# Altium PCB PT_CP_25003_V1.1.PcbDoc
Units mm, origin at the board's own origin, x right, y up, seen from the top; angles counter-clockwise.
Board outline 64.54 x 106 mm, 2 copper layers (Top Layer, Bottom Layer); 72 components, 59 nets, 203 pads, 41 vias.
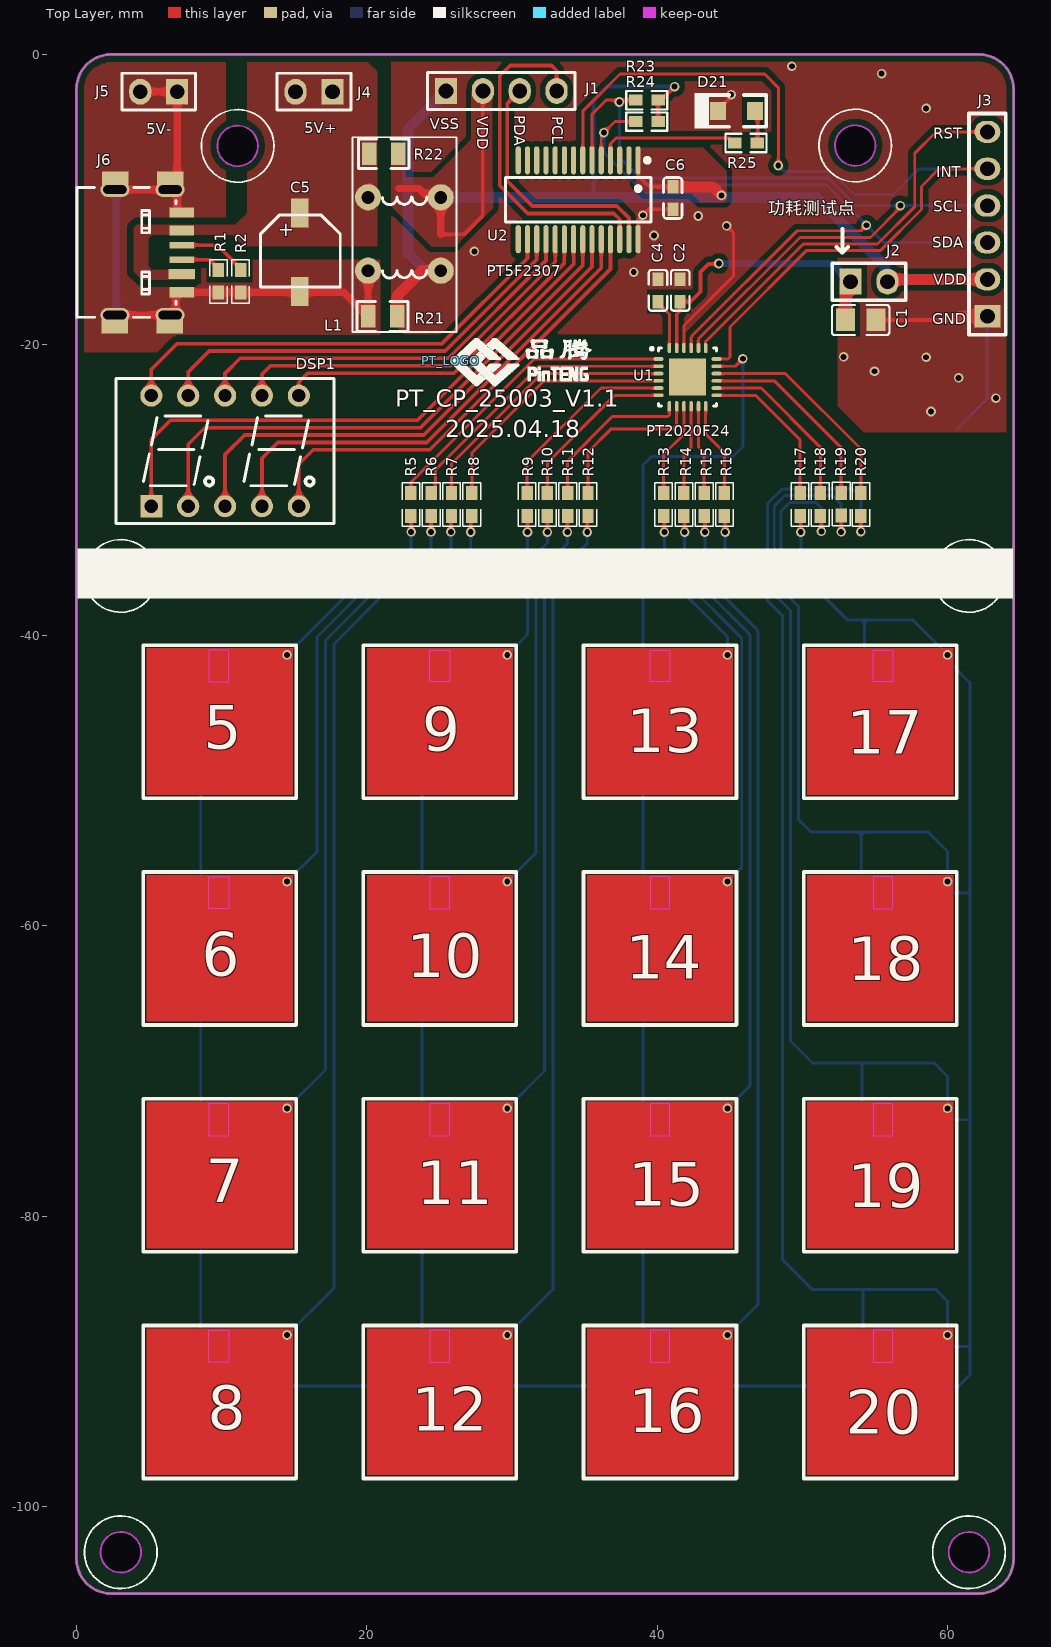
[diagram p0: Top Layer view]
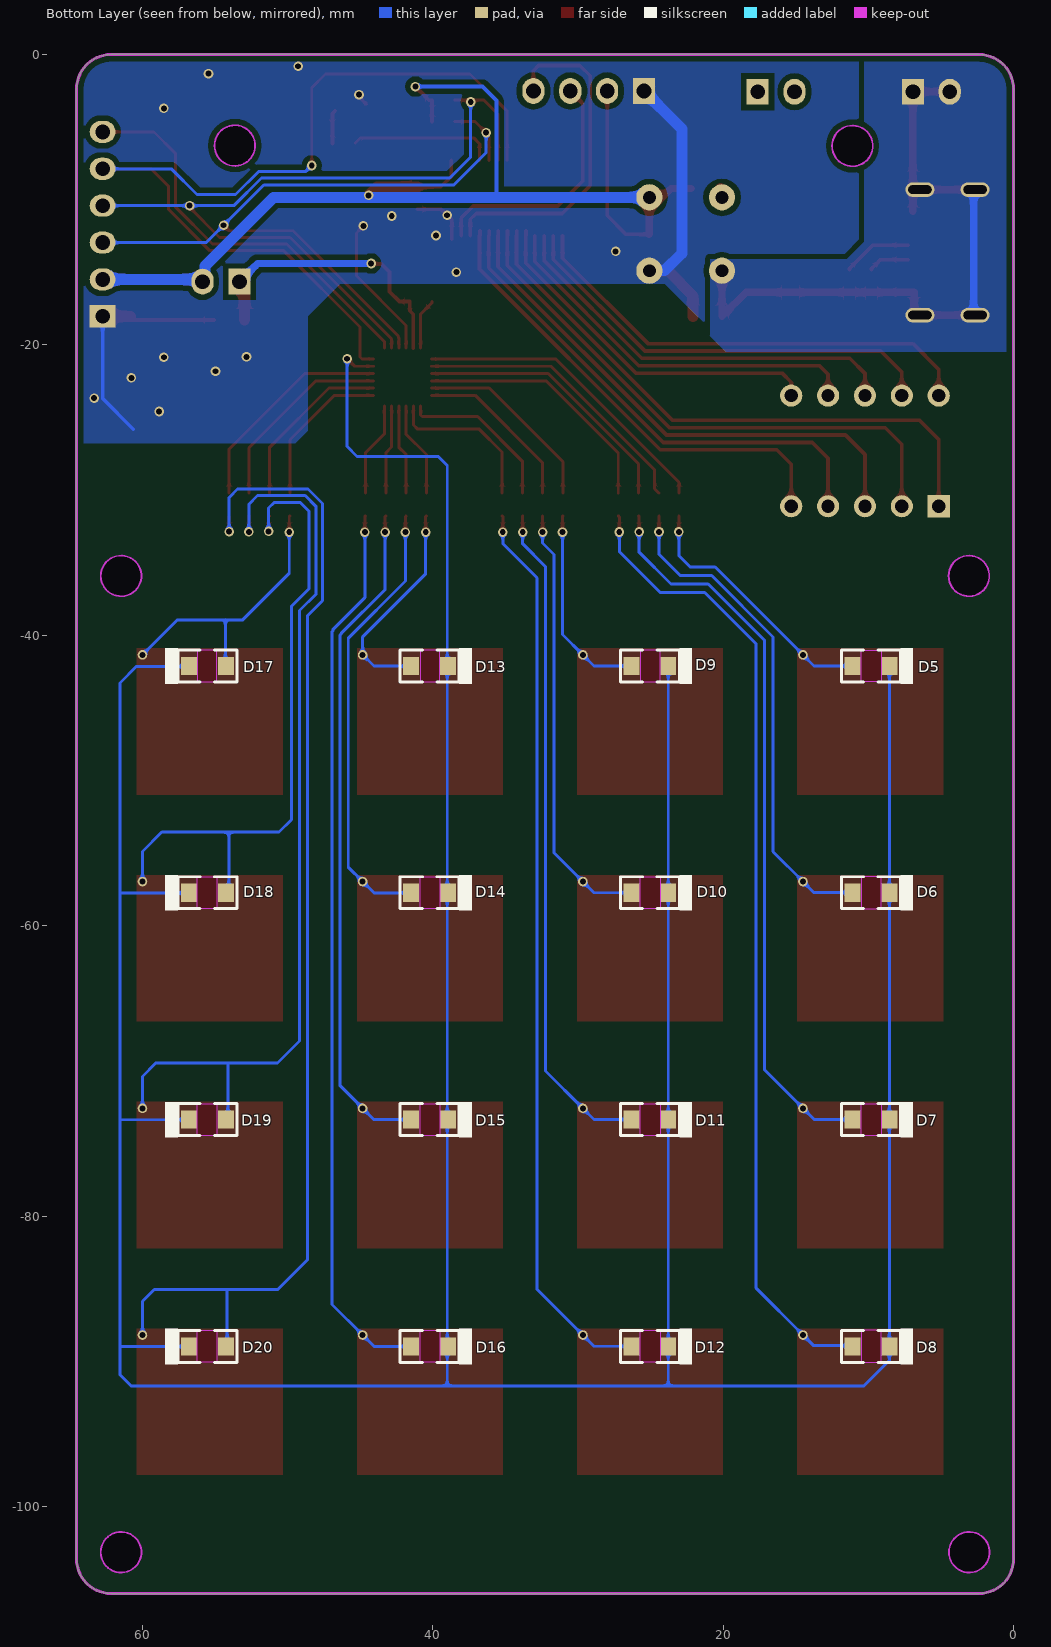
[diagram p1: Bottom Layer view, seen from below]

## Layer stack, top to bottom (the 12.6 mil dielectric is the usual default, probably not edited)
Top Solder: solder mask 0.0102, Solder Resist, Dk 3.5
Top Layer: signal copper 0.0356
Dielectric 1: dielectric 0.32, FR-4, Dk 4.8
Bottom Layer: signal copper 0.0356
Bottom Solder: solder mask 0.0102, Solder Resist, Dk 3.5

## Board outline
0,-103.612 0,-2.388 cw(c2.388,-2.388) 2.388,0 62.154,0 cw(c62.154,-2.388) 64.541,-2.388 64.541,-103.612 cw(c62.154,-103.612) 62.154,-106 2.388,-106 cw(c2.388,-103.612)
cut-out: 9.119,-90.083 9.119,-87.883 10.49,-87.883 10.49,-90.083
cut-out: 9.119,-43.22 10.49,-43.22 10.49,-41.02 9.119,-41.02
cut-out: 9.119,-58.835 9.119,-56.635 10.49,-56.635 10.49,-58.835
cut-out: 9.119,-74.462 10.49,-74.462 10.49,-72.262 9.119,-72.262
cut-out: 24.342,-74.462 25.713,-74.462 25.713,-72.262 24.342,-72.262
cut-out: 24.342,-90.083 25.713,-90.083 25.713,-87.883 24.342,-87.883
cut-out: 39.505,-90.083 40.877,-90.083 40.877,-87.883 39.505,-87.883
cut-out: 54.864,-90.083 56.235,-90.083 56.235,-87.883 54.864,-87.883
cut-out: 39.505,-74.462 40.877,-74.462 40.877,-72.262 39.505,-72.262
cut-out: 54.864,-74.462 56.235,-74.462 56.235,-72.262 54.864,-72.262
cut-out: 24.342,-58.835 25.713,-58.835 25.713,-56.635 24.342,-56.635
cut-out: 39.505,-58.835 40.877,-58.835 40.877,-56.635 39.505,-56.635
cut-out: 54.864,-58.835 56.235,-58.835 56.235,-56.635 54.864,-56.635
cut-out: 24.342,-43.22 24.342,-41.02 25.713,-41.02 25.713,-43.22
cut-out: 39.505,-43.22 39.505,-41.02 40.877,-41.02 40.877,-43.22
cut-out: 54.864,-43.22 54.864,-41.02 56.235,-41.02 56.235,-43.22
cut-out: 11.1,-7.699 cw(c11.1,-6.299) 9.7,-6.299 cw(c11.1,-6.299) 11.1,-4.899 cw(c11.1,-6.299) 12.5,-6.299 cw(c11.1,-6.299)
cut-out: 53.634,-7.674 cw(c53.634,-6.274) 52.234,-6.274 cw(c53.634,-6.274) 53.634,-4.874 cw(c53.634,-6.274) 55.034,-6.274 cw(c53.634,-6.274)
cut-out: 60.068,-35.916 ccw(c61.468,-35.916) 61.468,-37.316 ccw(c61.468,-35.916) 62.868,-35.916 ccw(c61.468,-35.916) 61.468,-34.516 ccw(c61.468,-35.916)
cut-out: 3.073,-37.316 cw(c3.073,-35.916) 1.673,-35.916 cw(c3.073,-35.916) 3.073,-34.516 cw(c3.073,-35.916) 4.473,-35.916 cw(c3.073,-35.916)
cut-out: 60.068,-103.155 ccw(c61.468,-103.155) 61.468,-104.555 ccw(c61.468,-103.155) 62.868,-103.155 ccw(c61.468,-103.155) 61.468,-101.755 ccw(c61.468,-103.155)
cut-out: 1.651,-103.155 ccw(c3.051,-103.155) 3.051,-104.555 ccw(c3.051,-103.155) 4.451,-103.155 ccw(c3.051,-103.155) 3.051,-101.755 ccw(c3.051,-103.155)

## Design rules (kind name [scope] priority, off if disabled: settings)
Clearance [All] p1: gap=0.381 except(0.254: Arc-Arc Arc-Track Track-Track)
PolygonConnect [All] p1: connectstyle=Direct reliefconductorwidth=0.254 reliefentries=4 polygonreliefangle="90 Angle" airgapwidth=0.254
RoutingVias [All] p1: holewidth=0.711 width=1.27 viastyle="Through Hole" minholewidth=0.711 minwidth=1.27 maxholewidth=0.711 maxwidth=1.27
SolderMaskExpansion [All] p1: expansion=0.102
SupplyNets "Schematic Supply Nets_4" [InNet('IGND')] p1: voltage=0.000
SupplyNets "Schematic Supply Nets_3" [InNet('VIN')] p2: voltage=0.000
SupplyNets "Schematic Supply Nets_1" [InNet('GND')] p3: voltage=0.000
SupplyNets "Schematic Supply Nets" [InNet('5V')] p4: voltage=0.000
Width [All] p1: maxlimit=2.54 minlimit=0.203 preferedwidth=0.203
30 further rules are at their usual default settings.

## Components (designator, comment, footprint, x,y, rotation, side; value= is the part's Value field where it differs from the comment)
5 "DOWN" "TP_10mm - H" 9.855,-45.923 r0 top
6 "DOWN" "TP_10mm - H" 9.855,-61.538 r0 top
7 "DOWN" "TP_10mm - H" 9.855,-77.153 r0 top
8 "DOWN" "TP_10mm - H" 9.855,-92.767 r0 top
9 "DOWN" "TP_10mm - H" 25.019,-45.923 r0 top
10 "DOWN" "TP_10mm - H" 25.019,-61.538 r0 top
11 "DOWN" "TP_10mm - H" 25.019,-77.153 r0 top
12 "DOWN" "TP_10mm - H" 25.019,-92.767 r0 top
13 "DOWN" "TP_10mm - H" 40.183,-45.923 r0 top
14 "DOWN" "TP_10mm - H" 40.183,-61.538 r0 top
15 "DOWN" "TP_10mm - H" 40.183,-77.153 r0 top
16 "DOWN" "TP_10mm - H" 40.183,-92.767 r0 top
17 "DOWN" "TP_10mm - H" 55.347,-45.923 r0 top
18 "DOWN" "TP_10mm - H" 55.347,-61.538 r0 top
19 "DOWN" "TP_10mm - H" 55.347,-77.153 r0 top
20 "DOWN" "TP_10mm - H" 55.347,-92.767 r0 top
C1 "10uF" C0805 52.959,-18.288 r0 top
C2 "0.1uF" C0603 41.58,-17.018 r90 top
C4 "20nF" C0603 40.056,-15.469 r270 top
C5 "100uF/16V" CS5.0 15.367,-10.922 r90 top
C6 "0.1uF" C0603 41.072,-9.119 r270 top
D5 "LED_B" LED_0805_F 11.1,-42.12 r180 bottom
D6 "LED_B" LED_0805_F 11.1,-57.735 r180 bottom
D7 "LED_B" LED_0805_F 11.1,-73.362 r180 bottom
D8 "LED_B" LED_0805_F 11.1,-88.983 r180 bottom
D9 "LED_B" LED_0805_F 26.323,-42.12 r180 bottom
D10 "LED_B" LED_0805_F 26.323,-57.735 r180 bottom
D11 "LED_B" LED_0805_F 26.323,-73.362 r180 bottom
D12 "LED_B" LED_0805_F 26.323,-88.983 r180 bottom
D13 "LED_B" LED_0805_F 41.487,-42.12 r180 bottom
D14 "LED_B" LED_0805_F 41.487,-57.735 r180 bottom
D15 "LED_B" LED_0805_F 41.487,-73.362 r180 bottom
D16 "LED_B" LED_0805_F 41.487,-88.983 r180 bottom
D17 "LED_B" LED_0805_F 54.254,-42.12 r0 bottom
D18 "LED_B" LED_0805_F 54.254,-57.734 r0 bottom
D19 "LED_B" LED_0805_F 54.254,-73.362 r0 bottom
D20 "LED_B" LED_0805_F 54.254,-88.983 r0 bottom
D21 "LED_B" LED_0805 46.736,-3.886 r180 top
DSP1 "CS2821AS" LED_2_0.28_2281 5.156,-31.115 r0 top
J1 "4PIN" D2.54_4P 25.451,-2.515 r0 top
J2 "2PIN" D2.54_2P 53.315,-15.646 r0 top
J3 "6PIN" D2.54_6P 62.738,-18.034 r90 top
J4 "2PIN" D2.54_2P 17.628,-2.565 r180 top
J5 "2PIN" D2.54_2P 6.934,-2.565 r180 top
J6 "Type-C母座" TYPE-C-6P 4.55,-13.63 r90 top
L1 "NC" L_10*5 25.087,-14.893 r180 top
PT_LOGO "PT_LOGO" PT_LOGO_2 25.781,-21.082 r0 top
R1 "5.1K" RES0603 9.779,-15.621 r90 top
R2 "5.1K" RES0603 11.303,-15.621 r90 top
R5 "470R" RES0603 23.038,-30.988 r270 top
R6 "470R" RES0603 24.435,-30.988 r270 top
R7 "470R" RES0603 25.832,-30.988 r270 top
R8 "470R" RES0603 27.229,-30.988 r270 top
R9 "470R" RES0603 31.039,-30.988 r270 top
R10 "470R" RES0603 32.436,-30.988 r270 top
R11 "470R" RES0603 33.833,-30.988 r270 top
R12 "470R" RES0603 35.23,-30.988 r270 top
R13 "470R" RES0603 40.437,-30.988 r270 top
R14 "470R" RES0603 41.834,-30.988 r270 top
R15 "470R" RES0603 43.231,-30.988 r270 top
R16 "470R" RES0603 44.628,-30.988 r270 top
R17 "470R" RES0603 49.835,-30.988 r270 top
R18 "470R" RES0603 51.232,-30.988 r270 top
R19 "470R" RES0603 52.667,-30.975 r270 top
R20 "470R" RES0603 54.026,-30.988 r270 top
R21 "0R" R0805 20.083,-18.043 r0 top
R22 "0R" R0805 20.168,-6.833 r0 top
R23 "4.7K" R0603 38.506,-3.15 r0 top
R24 "4.7K" R0603 38.506,-4.623 r0 top
R25 "470R" R0603 45.339,-6.096 r0 top
U1 "PT2020F24" QFN-24_4*4 42.088,-22.225 r0 top
U2 "PT5F2306P28" SSOP28_0.635 38.684,-7.29 r180 top

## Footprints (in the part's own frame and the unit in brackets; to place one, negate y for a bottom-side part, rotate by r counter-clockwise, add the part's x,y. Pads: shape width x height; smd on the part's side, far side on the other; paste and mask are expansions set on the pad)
C0603 [mil]
  rect 36.69x30 smd: 1(0,0) 2(61,0)
  silkscreen extent -25,-25 86,25
C0805 [mm]
  rect 1.3x1.55 smd: 1(0,0) 2(2.102,0)
  silkscreen extent -0.93,-1.04 3.03,1.04
CS5.0 [mm] "贴片电解电容"
  rect 2x1.2 smd: 1(0,0) 2(-5.4,0)
  silkscreen extent -5.1,-2.8 -0.15,2.71
D2.54_2P [mil] "接线端子"
  rect 60x70 hole 40: 1(0,0)
  oval 60x70 hole 40: 2(100,0)
  silkscreen extent -50,-50 150,50
D2.54_4P [mil] "接线端子"
  rect 60x70 hole 40: 1(0,0)
  oval 60x70 hole 40: 2(100,0) 3(200,0) 4(300,0)
  silkscreen extent -50,-50 350,50
D2.54_6P [mil] "接线端子"
  rect 60x70 hole 40: 1(0,0)
  oval 60x70 hole 40: 2(100,0) 3(200,0) 4(300,0) 5(400,0) 6(500,0)
  silkscreen extent -50,-50 550,50
L_10*5 [mm] "共模电感"
  round 1.8 hole 0.889: 1(0,0) 2(5,0) 3(0,-5.055) 4(5,-5.055)
  silkscreen extent -1.09,-9.19 6.07,4.22
LED_2_0.28_2281 [mil] "2*8数码管"
  rect 60x60 hole 36 mask+2: 1(0,0)
  round 60 hole 36 mask+2: 2(100,0) 3(200,0) 4(300,0) 5(400,0) 6(400,300) 7(300,300) 8(200,300) 9(100,300) 10(0,300)
  silkscreen extent -95,-47 495,347
LED_0805 [mm]
  rect 1.1x1.25 smd mask+0.051: 1(0,0) 2(2.54,0)
  silkscreen extent -0.76,-1.23 4.17,1.23
LED_0805_F [mm]
  rect 1.1x1.25 smd mask+0.051: 1(0,0) 2(2.54,0)
  silkscreen extent -0.76,-1.23 4.17,1.23
PT_LOGO_2 [mm]
  silkscreen extent 0,-1.73 9.7,1.55
QFN-24_4*4 [mm] "0.75"
  rect 2.55x2.55 smd: 0(0,0)
  oval 0.7x0.25 smd mask+0.08: 1(-2,1.25) 2(-2,0.75) 3(-2,0.25) 4(-2,-0.25) 5(-2,-0.75) 6(-2,-1.25) 13(2,-1.25) 14(2,-0.75) 15(2,-0.25) 16(2,0.25) 17(2,0.75) 18(2,1.25)
  oval 0.25x0.7 smd mask+0.08: 7(-1.25,-2) 8(-0.75,-2) 9(-0.25,-2) 10(0.25,-2) 11(0.75,-2) 12(1.25,-2) 19(1.25,2) 20(0.75,2) 21(0.25,2) 22(-0.25,2) 23(-0.75,2) 24(-1.25,2)
  silkscreen extent -2.56,-2 2,2.06, body extent -1.98,-2.01 2.01,1.98, height 0.3
R0603 [mil]
  rect 36.69x30 smd: 1(0,0) 2(61,0)
  silkscreen extent -25,-25 86,25
R0805 [mm]
  rect 1x1.55 smd: 1(0,0) 2(2,0)
  silkscreen extent -0.75,-1.02 2.75,1.02
RES0603 [mil]
  rect 38x31 smd: 1(-31,0) 2(31,0)
  silkscreen extent -59,-24 59,24, body extent -30,-15 33,16, height 18
SSOP28_0.635 [mil]
  oval 14x76.17 smd: 1(0,0) 2(25,0) 3(50,0) 4(75,0) 5(100,0) 6(125,0) 7(150,0) 8(175,0) 9(200,0) 10(225,0) 11(250,0) 12(275,0) 13(300,0) 14(325,0) 15(325,213.93) 16(300,213.93) 17(275,213.93) 18(250,213.93) 19(225,213.93) 20(200,213.93) 21(175,213.93) 22(150,213.93) 23(125,213.93) 24(100,213.93) 25(75,213.93) 26(50,213.93) 27(25,213.93) 28(0,213.93)
  silkscreen extent -35,-6 360,167
"TP_10mm - H" [mil]
  round 26 hole 16: 1(183,180)
  Top Layer region: -197,-199 -197,197.5 198,197.5 198,-199
  silkscreen extent -207,-209 208,206
TYPE-C-6P [mm]
  rect 1.016x1.829 smd: 0(-5.073,-1.885) 0(-5.073,1.915) 0(5.073,-1.915) 0(5.073,1.885)
  oval 1x2 hole 0.6 slot 1.6 at 90 deg: 0(-4.32,-1.9) 0(-4.32,1.9) 0(4.32,-1.9) 0(4.32,1.9)
  rect 0.45x1.7 smd: A5(0.5,-2.7) B5(-0.5,-2.7)
  rect 0.7x1.8 smd: A9(-1.5,-2.7)
  rect 0.7x1.7 smd: A12(-2.75,-2.7) B9(1.5,-2.7) B12(2.75,-2.7)
  silkscreen extent -4.47,-2.3 4.47,4.5

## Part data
5 6 7 8 9 10 11 12 13 14 15 16 17 18 19 20: library part TOUCH_SM, "TP"
C1 C2 C4: library part CAP3
C5: library part CAP2, "电解电容"
C6: library part CAP1, "电容"
D5 D6 D7 D8 D9 D10 D11 D12 D13 D14 D15 D16 D17 D18 D19 D20: library part LED0, "Typical INFRARED GaAs LED"
D21: library part LED
DSP1: library part LED_2, "2位数码管"
J6: library part Type-C-receptacle_6p, "Type-C 6P直插"
L1: library part "Trans Cupl", "Transformer (Coupled Inductor Model)"
R1 R2 R5 R6 R7 R8 R9 R10 R11 R12 R13 R14 R15 R16 R17 R18 R19 R20: library part Res, "Resistor"
R21 R22 R23 R24 R25: library part RES1, "电阻"
U1: "16键标品"
U2: library part PT109AP28, "MCU"

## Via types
v1: diameter 0.66, hole 0.406, Top Layer to Bottom Layer, tented both sides, 41 vias

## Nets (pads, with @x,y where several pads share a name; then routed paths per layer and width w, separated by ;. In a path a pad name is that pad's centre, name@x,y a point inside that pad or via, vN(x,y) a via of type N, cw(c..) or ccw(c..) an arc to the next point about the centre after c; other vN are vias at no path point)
5V: C6.1 J1.2 J2.2 J3.2 L1.3 R22.2 R23.2 R24.2 U2.1 | length 87.5
  Top Layer w0.254: 25.087,-12.393 26.697,-12.393 27.991,-11.1 J1.2 ; U2.1@38.735,-7.29 38.735,-8.363 38.713,-8.385 39.446,-9.119 C6.1 ; R24.2 R23.2 40.259,-3.15 v1(41.199,-2.21)
  Top Layer w0.508: 22.185,-9.229 23.58,-9.229 25.087,-10.736 25.087,-12.393
  Top Layer w0.762: C6.1 43.84,-9.119 v1(44.425,-9.703) ; J2.2@55.88,-15.265 56.109,-15.494 J3.2
  Bottom Layer w0.254: 35.662,-9.839 35.611,-9.788 35.611,-3.175 36.576,-2.21 v1(41.199,-2.21)
  Bottom Layer w0.762: L1.3 35.662,-9.839 50.961,-9.839 55.677,-14.554 55.677,-15.062 56.109,-15.494 J3.2
CC1: J6.A5 R2.2 | length 4.8
  Top Layer w0.254: J6.A5 9.688,-13.13 11.303,-14.745 R2.2
CC2: J6.B5 R1.2 | length 2.9
  Top Layer w0.254: J6.B5 9.164,-14.13 9.487,-14.453 9.779,-14.745 R1.2
GND: C1.2 C2.2 C4.1 C6.2 D21.2 J1.1 J3.1 L1.1 R21.2 U1.22 U2.28 | length 53.4
  Top Layer w0.203: U1.22 41.838,-18.665 45.263,-15.24 45.263,-12.294 v1(44.78,-11.811) ; D21.2@44.577,-3.429 v1@45.161,-2.845
  Top Layer w0.254: U2.28 38.684,-11.405 v1(39.014,-11.074) 39.421,-10.668 C6.2 ; C1.2 62.484,-18.288 J3.1
  Top Layer w0.762: R21.2 22.083,-16.627 23.816,-14.893 L1.1 ; 60.833,-18.034 J3.1
  Bottom Layer w0.254: 60.63,-25.806 62.738,-23.698 J3.1
  Bottom Layer w0.762: L1.1 24.037,-14.893 22.835,-13.691 22.835,-5.131 J1.1
  other v1: 58.852,-24.587 63.322,-23.673 60.757,-22.276 54.966,-21.819 58.522,-20.853 52.832,-20.828 38.379,-14.986 27.407,-13.564 39.776,-12.471 42.824,-11.125 58.522,-3.708 45.085,-2.769 55.448,-1.321 49.276,-0.813
I2C_SCL: J3.4 R23.1 U1.20 U2.6 | length 55.5
  Top Layer w0.203: U2.6 35.509,-4.115 36.474,-3.15 R23.1 ; U1.20 42.838,-19.586 49.825,-12.598 54.686,-12.598 56.744,-10.541 v1(56.744,-10.414)
  Bottom Layer w0.203: v1(37.389,-3.277) 37.389,-7.061 38.837,-8.509 51.802,-8.509 53.707,-10.414 v1(56.744,-10.414) J3.4
I2C_SDA: J3.3 R24.1 U1.21 U2.5 | length 50.9
  Top Layer w0.203: U2.5 36.144,-5.686 36.322,-5.509 v1(36.322,-5.385) 37.084,-4.623 R24.1 ; U1.21 42.338,-19.512 42.381,-19.47 42.381,-19.396 49.636,-12.141 54.026,-12.141 v1(54.407,-11.76)
  Bottom Layer w0.203: v1(36.322,-5.385) 36.322,-6.756 38.557,-8.992 51.638,-8.992 v1(54.407,-11.76) 55.601,-12.954 J3.3
IGND: C5.2 J5.1 J5.2 J6.0 J6.A12 J6.B12 L1.2 R1.1 R2.1 R21.1 | length 46
  Top Layer w0.508: J6.0@2.75,-17.95 4.343,-17.95 6.45,-17.95 6.85,-17.55 6.85,-16.38 9.525,-16.38 11.43,-16.38 12.344,-16.38 15.367,-16.38 18.42,-16.38 R21.1 20.083,-14.897 L1.2 ; J6.0@2.75,-9.31 6.45,-9.31 J6.0@6.819,-9.31 ; J5.2 J5.1 J6.B12@6.934,-10.795
  Bottom Layer w0.508: J6.0@2.75,-17.95 J6.0@2.75,-9.31
INT: J3.5 U1.18 U2.7 | length 65.8
  Top Layer w0.203: U2.7 34.874,-3.912 37.44,-1.346 47.396,-1.346 48.336,-2.286 v1(48.336,-7.645) ; U1.18 44.862,-20.975 45.009,-20.828 45.009,-18.771 50.267,-13.513 55.358,-13.513 58.191,-10.68 58.191,-9.093 59.411,-7.874 J3.5
  Bottom Layer w0.203: v1(48.336,-7.645) 48.743,-8.052 51.992,-8.052 53.592,-9.652 56.236,-9.652 58.014,-7.874 J3.5
LED_A: DSP1.7 U2.19 | length 26.7
  Top Layer w0.254: DSP1.7 12.776,-22.022 13.36,-21.438 25.814,-21.438 32.969,-14.282 U2.19@32.969,-12.495
LED_B: DSP1.8 U2.18 | length 28.5
  Top Layer w0.254: DSP1.8 10.236,-21.971 11.278,-20.93 25.603,-20.93 32.334,-14.199 U2.18@32.334,-12.495
LED_C: DSP1.3 U2.23 | length 36.7
  Top Layer w0.254: DSP1.3 10.236,-27.559 11.582,-26.213 23.912,-26.213 35.509,-14.616 U2.23@35.509,-12.495 ; U2.23@35.484,-12.495 U2.23@35.484,-12.139
LED_COM: D5.2 D6.2 D7.2 D8.2 D9.2 D10.2 D11.2 D12.2 D13.2 D14.2 D15.2 D16.2 D17.2 D18.2 D19.2 D20.2 U1.17 | length 297.8
  Top Layer w0.203: U1.17 45.376,-21.475 45.896,-20.955 v1(45.898,-20.955)
  Bottom Layer w0.203: D5.2@8.56,-42.113 D6.2 8.56,-73.349 8.56,-88.97 8.56,-89.943 10.31,-91.694 23.783,-91.694 ; D9.2 D10.2 D11.2 23.783,-88.976 23.783,-91.694 ; v1(45.898,-20.955) 45.898,-27 45.212,-27.686 39.624,-27.686 39.006,-28.304 39.006,-42.12 39.006,-57.734 39.006,-73.362 39.006,-88.977 39.006,-91.694 ; D18.2@56.591,-57.753 61.525,-57.753 61.544,-57.734 ; D19.2@56.65,-73.368 61.506,-73.368 ; D20.2@56.71,-88.983 61.487,-88.983 ; D17.2@56.82,-42.133 56.826,-42.139 60.401,-42.139 61.544,-43.282 61.544,-57.734 ; 23.783,-91.694 39.006,-91.694 ; 39.006,-91.694 60.78,-91.694 61.544,-90.93 61.544,-88.983 61.544,-73.368 61.544,-57.734
LED_D: DSP1.2 U2.22 | length 38.9
  Top Layer w0.254: DSP1.2 7.696,-26.848 8.839,-25.705 23.702,-25.705 34.874,-14.532 U2.22@34.874,-12.495 ; U2.22@34.849,-12.495 U2.22@34.849,-12.139
LED_DP: DSP1.5 U2.25 | length 32.6
  Top Layer w0.254: DSP1.5 15.316,-28.219 16.307,-27.229 24.333,-27.229 36.779,-14.783 U2.25@36.779,-12.495 ; U2.25@36.754,-12.495 U2.25@36.754,-12.139
LED_E: DSP1.1 U2.21 | length 41
  Top Layer w0.254: DSP1.1 5.156,-26.518 6.477,-25.197 23.491,-25.197 34.239,-14.449 U2.21@34.239,-12.495 ; U2.21@34.214,-12.495 U2.21@34.214,-12.139
LED_F: DSP1.10 U2.16 | length 32.4
  Top Layer w0.254: DSP1.10 5.156,-21.692 6.934,-19.914 25.182,-19.914 31.064,-14.032 U2.16@31.064,-12.495
LED_G: DSP1.4 U2.24 | length 34.7
  Top Layer w0.254: DSP1.4 12.776,-27.813 13.868,-26.721 24.123,-26.721 36.144,-14.699 U2.24@36.144,-12.495 ; U2.24@36.119,-12.495 U2.24@36.119,-12.139
LED_G1: DSP1.9 U2.17 | length 30.5
  Top Layer w0.254: DSP1.9 7.696,-21.869 9.144,-20.422 25.393,-20.422 31.699,-14.115 U2.17@31.699,-12.495
LED_G2: DSP1.6 U2.20 | length 24.8
  Top Layer w0.254: DSP1.6 15.316,-22.581 15.951,-21.946 26.024,-21.946 33.604,-14.365 U2.20@33.604,-12.495 ; U2.20@33.579,-12.495 U2.20@33.579,-12.139
MCU_RX0: J1.4 U2.26 | length 23.7
  Top Layer w0.254: J1.4 33.071,-1.118 32.715,-0.762 29.87,-0.762 29.159,-1.473 29.159,-9.017 31.09,-10.947 37.008,-10.947 37.414,-11.354 U2.26@37.414,-12.495
MCU_TX0: J1.3 U2.27 | length 17.6
  Top Layer w0.254: J1.3@30.531,-2.896 J1.3 29.667,-3.378 29.667,-8.712 31.394,-10.439 37.218,-10.439 38.049,-11.27 U2.27@38.049,-12.495
Net5_1: 5.1 D5.1 R5.2 | length 17.9
  Top Layer w0.203: R5.2 23.052,-31.79 v1(23.052,-32.879)
  Bottom Layer w0.203: D5.1@11.1,-42.113 13.741,-42.113 5.1 20.549,-35.306 22.276,-35.306 23.052,-34.53 v1(23.052,-32.879)
Net6_1: 6.1 D6.1 R6.2 | length 34.2
  Top Layer w0.203: v1(24.42,-32.882) 24.42,-31.79 R6.2
  Bottom Layer w0.203: D6.1@11.159,-57.728 13.741,-57.728 6.1 16.561,-54.908 16.561,-40.12 20.791,-35.89 22.957,-35.89 24.42,-34.428 v1(24.42,-32.882)
Net7_1: 7.1 D7.1 R7.2 | length 50.6
  Top Layer w0.203: v1(25.788,-32.886) 25.788,-31.819 R7.2
  Bottom Layer w0.203: D7.1@11.218,-73.342 13.741,-73.342 7.1 17.145,-69.939 17.145,-40.362 21.033,-36.474 23.597,-36.474 25.788,-34.283 v1(25.788,-32.886)
Net8_1: 8.1 D8.1 R8.2 | length 67
  Top Layer w0.203: v1(27.156,-32.889) 27.156,-31.848 R8.2
  Bottom Layer w0.203: D8.1@11.328,-88.932 13.767,-88.932 8.1 17.729,-84.969 17.729,-40.604 21.275,-37.059 24.333,-37.059 27.156,-34.236 v1(27.156,-32.889)
Net9_1: 9.1 D9.1 R9.2 | length 13.8
  Top Layer w0.203: R9.2 31.064,-31.801 v1(31.064,-32.893)
  Bottom Layer w0.203: D9.1 28.899,-42.12 9.1 31.064,-39.954 v1(31.064,-32.893)
Net10_1: 10.1 D10.1 R10.2 | length 29.9
  Top Layer w0.203: v1(32.436,-32.893) R10.2
  Bottom Layer w0.203: D10.1@26.382,-57.734 28.899,-57.734 10.1 31.648,-54.985 31.648,-34.442 32.436,-33.655 v1(32.436,-32.893)
Net11_1: 11.1 D11.1 R11.2 | length 46
  Top Layer w0.203: v1(33.807,-32.893) 33.807,-31.801 R11.2
  Bottom Layer w0.203: D11.1@26.492,-73.349 28.899,-73.349 11.1 32.233,-70.015 32.233,-35.281 33.807,-33.706 v1(33.807,-32.893)
Net12_1: 12.1 D12.1 R12.2 | length 62.4
  Top Layer w0.203: v1(35.179,-32.893) 35.179,-31.826 R12.2
  Bottom Layer w0.203: D12.1@26.264,-88.97 28.892,-88.97 12.1 32.817,-85.046 32.817,-36.043 35.179,-33.68 v1(35.179,-32.893)
Net13_1: 13.1 D13.1 R13.2 | length 15
  Top Layer w0.203: R13.2 40.488,-31.826 v1(40.488,-32.893)
  Bottom Layer w0.203: v1(40.488,-32.893) 40.488,-35.763 44.831,-40.107 13.1 44.056,-42.126 D13.1@41.546,-42.126
Net14_1: 14.1 D14.1 R14.2 | length 30.7
  Top Layer w0.203: R14.2 41.885,-31.826 v1(41.885,-32.893)
  Bottom Layer w0.203: D14.1@41.656,-57.741 44.056,-57.741 14.1 45.822,-55.975 45.822,-40.208 41.885,-36.271 v1(41.885,-32.893)
Net15_1: 15.1 D15.1 R15.2 | length 46.5
  Top Layer w0.203: R15.2 43.282,-31.826 v1(43.282,-32.893)
  Bottom Layer w0.203: D15.1@41.427,-73.362 44.05,-73.362 15.1 46.38,-71.031 46.38,-39.977 46.304,-39.901 46.304,-39.865 43.282,-36.842 v1(43.282,-32.893)
Net16_1: 16.1 D16.1 R16.2 | length 61.9
  Top Layer w0.203: R16.2 44.679,-31.826 v1(44.679,-32.893)
  Bottom Layer w0.203: D16.1@41.546,-88.977 44.05,-88.977 16.1 46.939,-86.087 46.939,-39.745 46.888,-39.694 46.888,-39.623 44.679,-37.413 v1(44.679,-32.893)
Net17_1: 17.1 D17.1 R17.2 | length 19.6
  Top Layer w0.203: R17.2 49.886,-31.826 v1(49.886,-32.893)
  Bottom Layer w0.203: v1(49.886,-32.893) 49.886,-35.738 53.086,-38.938 54.28,-38.938 ; D17.1@54.28,-42.133 54.28,-38.938 ; 17.1 57.582,-38.938 54.28,-38.938
Net18_1: 18.1 D18.1 R18.2 | length 45.1
  Top Layer w0.203: R18.2 51.308,-31.852 v1(51.308,-32.842)
  Bottom Layer w0.203: v1(51.308,-32.842) 51.308,-31.242 50.927,-30.861 49.124,-30.861 48.514,-31.471 48.514,-36.779 49.733,-37.998 49.733,-52.705 50.584,-53.556 58.661,-53.556 59.995,-54.889 18.1 ; D18.1@54.051,-57.753 54.051,-53.556
Net19_1: 19.1 D19.1 R19.2 | length 63.4
  Top Layer w0.203: v1(52.667,-32.88) R19.2
  Bottom Layer w0.203: v1(52.667,-32.88) 52.667,-30.975 52.07,-30.378 48.791,-30.378 48.057,-31.113 48.057,-37.186 49.174,-38.303 49.174,-67.945 50.698,-69.469 54.102,-69.469 ; D19.1@54.11,-73.368 54.11,-69.477 54.102,-69.469 ; 19.1 59.995,-70.383 59.08,-69.469 54.102,-69.469
Net20_1: 20.1 D20.1 R20.2 | length 81.8
  Top Layer w0.203: v1(54.026,-32.868) R20.2
  Bottom Layer w0.203: v1(54.026,-32.868) 54.026,-30.505 53.442,-29.921 48.602,-29.921 47.6,-30.923 47.6,-37.617 48.616,-38.633 48.616,-68.176 48.641,-68.202 48.641,-83.033 50.673,-85.065 59.182,-85.065 59.995,-85.877 20.1 ; D20.1@54.17,-88.983 54.17,-85.082
NetC1_1: C1.1 C2.1 J2.1 U1.23 | length 20.3
  Top Layer w0.254: U1.23 41.338,-17.892 41.58,-17.65 C2.1 42.3,-17.018 42.977,-16.341 42.977,-14.986 43.536,-14.427 44.215,-14.427 v1(44.247,-14.396)
  Top Layer w0.762: C1.1 52.959,-16.002 J2.1
  Bottom Layer w0.508: v1(44.247,-14.396) 52.064,-14.396 52.68,-15.011 52.807,-15.011 53.315,-15.519 J2.1
NetC4_2: C4.2 U1.24 | length 3.5
  Top Layer w0.203: C4.2 40.056,-17.103 40.838,-17.885 U1.24
NetD21_1: D21.1 R25.2 | length 2.3
  Top Layer w0.254: D21.1 46.914,-4.064 R25.2@46.914,-6.147
OUT: R25.1 U2.4 | length 10
  Top Layer w0.203: U2.4 36.779,-6.147 37.186,-5.74 44.069,-5.74 44.983,-5.74 R25.1
RST: J3.6 U1.19 | length 28
  Top Layer w0.203: U1.19 43.338,-19.774 50.057,-13.056 55.169,-13.056 57.734,-10.49 57.734,-6.807 59.207,-5.334 J3.6
TCH5: R5.1 U1.1 | length 21.3
  Top Layer w0.203: R5.1 23.038,-29.466 31.528,-20.975 U1.1
TCH6: R6.1 U1.2 | length 20
  Top Layer w0.203: R6.1 24.727,-29.909 24.727,-28.603 31.855,-21.475 U1.2
TCH7: R7.1 U1.3 | length 18.8
  Top Layer w0.203: R7.1 25.832,-28.194 32.051,-21.975 U1.3
TCH8: R8.1 U1.4 | length 17.7
  Top Layer w0.203: R8.1 27.229,-27.444 32.197,-22.475 U1.4
TCH9: R9.1 U1.5 | length 13.3
  Top Layer w0.203: R9.1 31.039,-28.054 36.118,-22.975 U1.5
TCH10: R10.1 U1.6 | length 11.7
  Top Layer w0.203: R10.1 32.436,-28.118 37.079,-23.475 U1.6
TCH11: R11.1 U1.7 | length 11.1
  Top Layer w0.203: R11.1 33.833,-28.016 36.906,-24.943 40.719,-24.943 40.838,-24.824 U1.7
TCH12: R12.1 U1.8 | length 11
  Top Layer w0.203: R12.1 35.23,-27.381 36.83,-25.781 41.072,-25.781 41.338,-25.515 U1.8
TCH13: R13.1 U1.9 | length 6.6
  Top Layer w0.203: R13.1 40.437,-27.559 41.838,-26.158 U1.9
TCH14: R14.1 U1.10 | length 6.2
  Top Layer w0.203: R14.1 41.834,-27.559 42.338,-27.055 U1.10
TCH15: R15.1 U1.11 | length 6.1
  Top Layer w0.203: U1.11 42.838,-27.039 43.231,-27.432 R15.1
TCH16: R16.1 U1.12 | length 6.5
  Top Layer w0.203: U1.12 43.338,-26.142 44.628,-27.432 R16.1
TCH17: R17.1 U1.13 | length 10.7
  Top Layer w0.203: U1.13 46.767,-23.475 49.835,-26.543 R17.1
TCH18: R18.1 U1.14 | length 12
  Top Layer w0.203: U1.14 47.156,-22.975 51.232,-27.051 R18.1
TCH19: R19.1 U1.15 | length 13.6
  Top Layer w0.203: U1.15 48.053,-22.475 52.667,-27.089 R19.1
TCH20: R20.1 U1.16 | length 15.1
  Top Layer w0.203: U1.16 48.823,-21.975 54.026,-27.178 R20.1
VIN: C5.1 J4.1 J4.2 J6.A9 J6.B9 L1.4 R22.1 | length 0.1
  Top Layer w0.762: L1.4@20.087,-9.327 L1.4@20.185,-9.229
pads on no net: U1.0 U2.2 U2.3 U2.8 U2.9 U2.10 U2.11 U2.12 U2.13 U2.14 U2.15

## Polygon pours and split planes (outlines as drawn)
GND on Top Layer "Top Layer-No Net" (solid, remove dead copper, pour order 48): 21.686,-8.519 21.686,-0.01 62.662,-0.01 63.75,-0.644 64.46,-1.808 64.536,-1.884 64.536,-26.02 54.223,-26.02 52.395,-24.191 52.42,-24.165 52.42,-17.061 52.42,-14.776 52.42,-13.847 52.395,-14.75 46.781,-14.75 46.781,-17.409 45.029,-19.162 44.927,-19.263 29.208,-19.263 22.568,-19.263 21.577,-18.273 21.686,-18.164
5V on Top Layer "Top Layer-No Net 1" (solid, pour order 46): 38.811,-6.426 43.18,-6.426 44.552,-7.798 44.78,-8.026 44.78,-10.008 44.78,-10.033 44.628,-10.185 43.688,-10.185 42.951,-10.185 42.443,-9.677 42.342,-9.576 40.691,-9.576 39.141,-9.576 38.557,-8.992 38.506,-8.941 38.506,-6.604 38.506,-6.477 38.557,-6.426 38.811,-6.426
5V on Top Layer "Top Layer-No Net" (solid, remove dead copper, pour order 4): 28.702,-2.489 28.702,-10.566 26.213,-13.056 26.035,-13.233 24.714,-13.233 24.46,-13.233 23.393,-12.167 21.692,-10.465 21.692,-7.239 22.631,-7.239 22.631,-8.458 24.587,-8.458 26.518,-6.528 27.203,-5.842 27.203,-2.489 28.677,-2.489 28.702,-2.515
VIN on Top Layer "VIN_L01_P049" (hatched Horizontal grid 0 track 0.1, remove dead copper, pour order 49): 20.701,-13.208 20.701,-1.168 20.025,-0.492 11.76,-0.492 11.76,-10.922 10.973,-11.71 4.165,-11.71 3.937,-11.938 3.937,-14.947 4.5,-15.51 8.112,-15.51 8.128,-15.494 8.128,-14.859 5.207,-14.859 4.953,-14.605 4.953,-12.7 5.207,-12.446 10.795,-12.446 11.557,-13.208
IGND on Top Layer "IGND_L01_P050" (hatched Horizontal grid 0 track 0.1, remove dead copper, pour order 50): 20.879,-14.097 11.481,-14.097 10.287,-12.903 10.287,-0.025 10.274,-0.013 1.388,-0.013 -0.051,-1.451 -0.051,-20.472 19.837,-20.472 20.93,-19.38 20.93,-14.148
IGND on Bottom Layer "Top Layer-No Net" (solid, remove dead copper, pour order 16): 9.601,0 1.422,0 0,-1.422 -0.051,-1.473 -0.051,-6.045 -0.051,-20.472 5.918,-20.472 19.837,-20.472 20.93,-19.38 20.879,-19.329 20.879,-14.097 11.481,-14.097 10.592,-13.208 10.287,-12.903 10.287,-4.877 10.287,-0.025 10.262,0 9.576,0
GND on Bottom Layer "Top Layer-No Net" (solid, remove dead copper, pour order 42): -0.001,-20.35 -0.001,-1.604 -0.102,-1.503 1.371,-0.03 62.61,-0.03 62.864,-0.03 62.991,-0.03 64.363,-1.401 64.49,-1.528 64.49,-26.776 49.478,-26.776 49.275,-26.573 48.619,-25.916 48.619,-22.86 48.619,-18.034 46.369,-15.785 31.344,-15.785 24.021,-15.785 23.113,-16.692 21.945,-17.86 21.419,-18.386 20.573,-19.232 19.456,-20.35 18.744,-20.35 0.904,-20.35

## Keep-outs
Keep-Out Layer:
  circle w0.127: c61.468,-35.916 r1.4
  circle w0.127: c3.073,-35.916 r1.4
  circle w0.127: c61.468,-103.155 r1.4
  circle w0.127: c3.051,-103.155 r1.4
  circle w0.127: c53.634,-6.274 r1.4
  circle w0.127: c11.1,-6.299 r1.4
  lines w0.203: 0,-103.612 ccw(c2.388,-103.612) 2.388,-106 62.154,-106 ccw(c62.154,-103.612) 64.541,-103.612 64.541,-2.388 ccw(c62.154,-2.388) 62.154,0 2.388,0 ccw(c2.388,-2.388) 0,-2.388 0,-103.612

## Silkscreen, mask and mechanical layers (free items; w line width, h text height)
Top Overlay:
  circle w0.127: c61.468,-35.916 r2.5
  circle w0.127: c3.051,-35.916 r2.5
  circle w0.127: c53.634,-6.274 r2.5
  circle w0.127: c11.1,-6.299 r2.5
  circle w0.127: c61.468,-103.155 r2.5
  circle w0.127: c3.051,-103.155 r2.5
  rectangle: 0.076,-37.465 64.516,-34.011
  lines w0.254: 52.349,-13.259 52.73,-13.64 ; 52.756,-12.014 52.756,-13.64 53.137,-13.259
  text "PDA" at 30.15,-4.191 h0.76 r270
  text "VDD" at 27.61,-4.242 h0.76 r270
  text "PCL" at 32.766,-4.242 h0.76 r270
  text "VSS" at 24.333,-5.156 h0.76
  text "5V+" at 15.697,-5.436 h0.76
  text "5V-" at 4.801,-5.512 h0.76
  text "RST" at 59.004,-5.791 h0.76
  text "INT" at 59.233,-8.458 h0.76
  text "SCL" at 59.004,-10.846 h0.76
  text "功耗测试点" at 47.625,-11.303 h1.52
  text "SDA" at 58.928,-13.31 h0.76
  text "PT5F2307" at 28.27,-15.265 h0.76
  text "VDD" at 59.004,-15.875 h0.76
  text "GND" at 58.953,-18.593 h0.76
  text "PT_CP_25003_V1.1" at 21.971,-24.66 h2.03
  text "PT2020F24" at 39.243,-26.289 h0.76
  text "2025.04.18" at 25.4,-26.773 h2.03
Mechanical 1:
  circle w0.127: c61.468,-35.916 r1.4
  circle w0.127: c3.073,-35.916 r1.4
  circle w0.127: c53.634,-6.274 r1.4
  circle w0.127: c11.1,-6.299 r1.4
  circle w0.127: c61.468,-103.155 r1.4
  circle w0.127: c3.051,-103.155 r1.4
  lines w0.127: 9.119,-90.083 9.119,-87.883 10.49,-87.883 10.49,-90.083 9.119,-90.083 ; 9.119,-74.462 9.119,-72.262 10.49,-72.262 10.49,-74.462 9.119,-74.462 ; 9.119,-58.835 9.119,-56.635 10.49,-56.635 10.49,-58.835 9.119,-58.835 ; 9.119,-43.22 10.49,-43.22 10.49,-41.02 9.119,-41.02 9.119,-43.22 ; 24.342,-90.083 25.713,-90.083 25.713,-87.883 24.342,-87.883 24.342,-90.083 ; 24.342,-74.462 25.713,-74.462 25.713,-72.262 24.342,-72.262 24.342,-74.462 ; 24.342,-58.835 25.713,-58.835 25.713,-56.635 24.342,-56.635 24.342,-58.835 ; 24.342,-43.22 24.342,-41.02 25.713,-41.02 25.713,-43.22 24.342,-43.22 ; 39.505,-90.083 40.877,-90.083 40.877,-87.883 39.505,-87.883 39.505,-90.083 ; 39.505,-74.462 40.877,-74.462 40.877,-72.262 39.505,-72.262 39.505,-74.462 ; 39.505,-58.835 40.877,-58.835 40.877,-56.635 39.505,-56.635 39.505,-58.835 ; 39.505,-43.22 39.505,-41.02 40.877,-41.02 40.877,-43.22 39.505,-43.22 ; 54.864,-90.083 56.235,-90.083 56.235,-87.883 54.864,-87.883 54.864,-90.083 ; 54.864,-74.462 56.235,-74.462 56.235,-72.262 54.864,-72.262 54.864,-74.462 ; 54.864,-58.835 56.235,-58.835 56.235,-56.635 54.864,-56.635 54.864,-58.835 ; 54.864,-43.22 54.864,-41.02 56.235,-41.02 56.235,-43.22 54.864,-43.22
  lines w0.203: 0,-103.612 ccw(c2.388,-103.612) 2.388,-106 62.154,-106 ccw(c62.154,-103.612) 64.541,-103.612 64.541,-2.388 ccw(c62.154,-2.388) 62.154,0 2.388,0 ccw(c2.388,-2.388) 0,-2.388 0,-103.612
Mechanical 11:
  lines w0.127: -1.092,0 2.388,0 ; 0,-2.388 0,1.092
